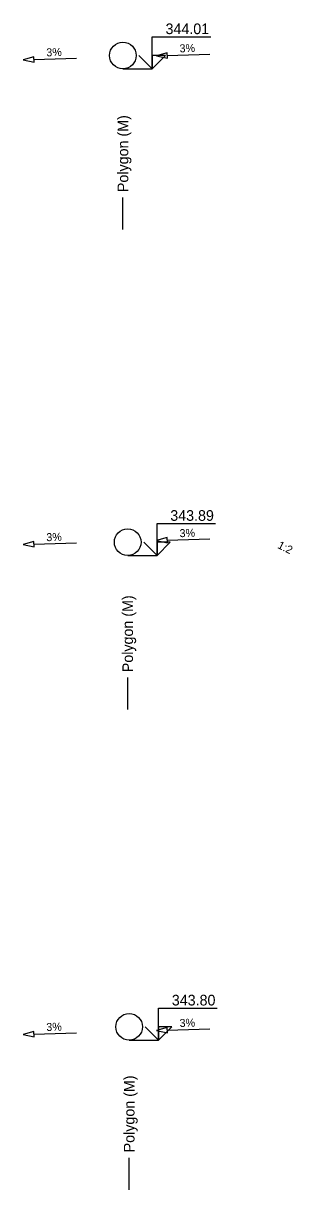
# Model space of a CAD drawing. Extents: x 1989 to 2511, y -2653 to -2294.
# Drawn here: x 2087.48 to 2092.53, y -2325.47 to -2303.61 of the extents above; entities that cross this region are included whole.
import ezdxf

# ---------------------------------------------------------------- set-up
doc = ezdxf.new("R2010")
doc.units = 0
for name, color, linetype in [('KOTA_AUTOMAT', 7, 'Continuous'), ('KRIZENI_AUTOMAT', 7, 'Continuous'), ('POPISY_NAD_TERENEM', 7, 'Continuous'), ('SKLON', 7, 'Continuous')]:
    doc.layers.add(name, color=color, linetype=linetype)

msp = doc.modelspace()

# ---------------------------------------------------------------- linework, layer by layer
at = {"layer": 'KOTA_AUTOMAT'}
for points in [[(2089.896, -2304.462), (2089.646, -2304.212), (2089.896, -2304.462), (2089.896, -2303.862), (2090.996, -2303.862)], [(2089.896, -2304.462), (2090.146, -2304.212), (2089.896, -2304.212), (2089.896, -2304.462)], [(2089.896, -2304.462), (2090.146, -2304.212), (2089.896, -2304.212)], [(2089.346, -2304.462), (2089.896, -2304.462)], [(2089.985, -2313.585), (2089.735, -2313.335), (2089.985, -2313.585), (2089.985, -2312.985), (2091.085, -2312.985)], [(2089.985, -2313.585), (2090.235, -2313.335), (2089.985, -2313.335), (2089.985, -2313.585)], [(2089.985, -2313.585), (2090.235, -2313.335), (2089.985, -2313.335)], [(2089.435, -2313.585), (2089.985, -2313.585)], [(2090.013, -2322.67), (2089.763, -2322.42), (2090.013, -2322.67), (2090.013, -2322.07), (2091.113, -2322.07)], [(2090.013, -2322.67), (2090.263, -2322.42), (2090.013, -2322.42), (2090.013, -2322.67)], [(2090.013, -2322.67), (2090.263, -2322.42), (2090.013, -2322.42)], [(2089.463, -2322.67), (2090.013, -2322.67)]]:
    msp.add_lwpolyline(points, dxfattribs=at)
at = {"layer": 'KRIZENI_AUTOMAT'}
for centre in [(2089.346, -2304.212), (2089.435, -2313.335), (2089.463, -2322.42)]:
    msp.add_circle(centre, 0.25, dxfattribs=at)
at = {"layer": 'POPISY_NAD_TERENEM'}
for points in [[(2089.346, -2307.473), (2089.346, -2306.873)], [(2089.435, -2316.473), (2089.435, -2315.873)], [(2089.463, -2325.473), (2089.463, -2324.873)]]:
    msp.add_lwpolyline(points, dxfattribs=at)
at = {"layer": 'SKLON'}
for points in [[(2090.176, -2304.161), (2089.977, -2304.217), (2090.179, -2304.261)], [(2087.676, -2304.236), (2087.477, -2304.292), (2087.679, -2304.336)], [(2087.676, -2313.324), (2087.477, -2313.38), (2087.679, -2313.424)], [(2090.176, -2313.249), (2089.977, -2313.305), (2090.179, -2313.349)], [(2087.676, -2322.506), (2087.477, -2322.562), (2087.679, -2322.606)], [(2090.176, -2322.431), (2089.977, -2322.487), (2090.179, -2322.531)]]:
    msp.add_lwpolyline(points, close=True, dxfattribs=at)
for points in [[(2090.179, -2304.261), (2090.176, -2304.161), (2089.977, -2304.217), (2090.179, -2304.261)], [(2090.177, -2304.211), (2090.977, -2304.187)], [(2087.679, -2304.336), (2087.676, -2304.236), (2087.477, -2304.292), (2087.679, -2304.336)], [(2087.677, -2304.286), (2088.477, -2304.262)], [(2087.679, -2313.424), (2087.676, -2313.324), (2087.477, -2313.38), (2087.679, -2313.424)], [(2087.677, -2313.374), (2088.477, -2313.35)], [(2090.179, -2313.349), (2090.176, -2313.249), (2089.977, -2313.305), (2090.179, -2313.349)], [(2090.177, -2313.299), (2090.977, -2313.275)], [(2087.679, -2322.606), (2087.676, -2322.506), (2087.477, -2322.562), (2087.679, -2322.606)], [(2087.677, -2322.556), (2088.477, -2322.532)], [(2090.179, -2322.531), (2090.176, -2322.431), (2089.977, -2322.487), (2090.179, -2322.531)], [(2090.177, -2322.481), (2090.977, -2322.457)]]:
    msp.add_lwpolyline(points, dxfattribs=at)

# ---------------------------------------------------------------- texts
at = {"layer": 'KOTA_AUTOMAT'}
for s, p in [('344.01', (2090.145, -2303.812)), ('343.89', (2090.234, -2312.935)), ('343.80', (2090.263, -2322.02))]:
    msp.add_text(s, height=0.2, dxfattribs=at).set_placement(p)
at = {"layer": 'POPISY_NAD_TERENEM'}
for p in [(2089.446, -2306.773), (2089.535, -2315.773), (2089.563, -2324.773)]:
    msp.add_text('Polygon (M)', height=0.2, rotation=90, dxfattribs=at).set_placement(p)
at = {"layer": 'SKLON'}
for s, rotation, p in [('3%', 1.7184, (2087.911, -2304.229)), ('3%', 1.7184, (2090.411, -2304.154)), ('3%', 1.7184, (2090.411, -2313.242)), ('3%', 1.7184, (2087.911, -2313.317)), ('1:2', 333.4349, (2092.233, -2313.439)), ('3%', 1.7184, (2090.411, -2322.424)), ('3%', 1.7184, (2087.911, -2322.499))]:
    msp.add_text(s, height=0.15, rotation=rotation, dxfattribs=at).set_placement(p)

doc.saveas('drawing.dxf')
